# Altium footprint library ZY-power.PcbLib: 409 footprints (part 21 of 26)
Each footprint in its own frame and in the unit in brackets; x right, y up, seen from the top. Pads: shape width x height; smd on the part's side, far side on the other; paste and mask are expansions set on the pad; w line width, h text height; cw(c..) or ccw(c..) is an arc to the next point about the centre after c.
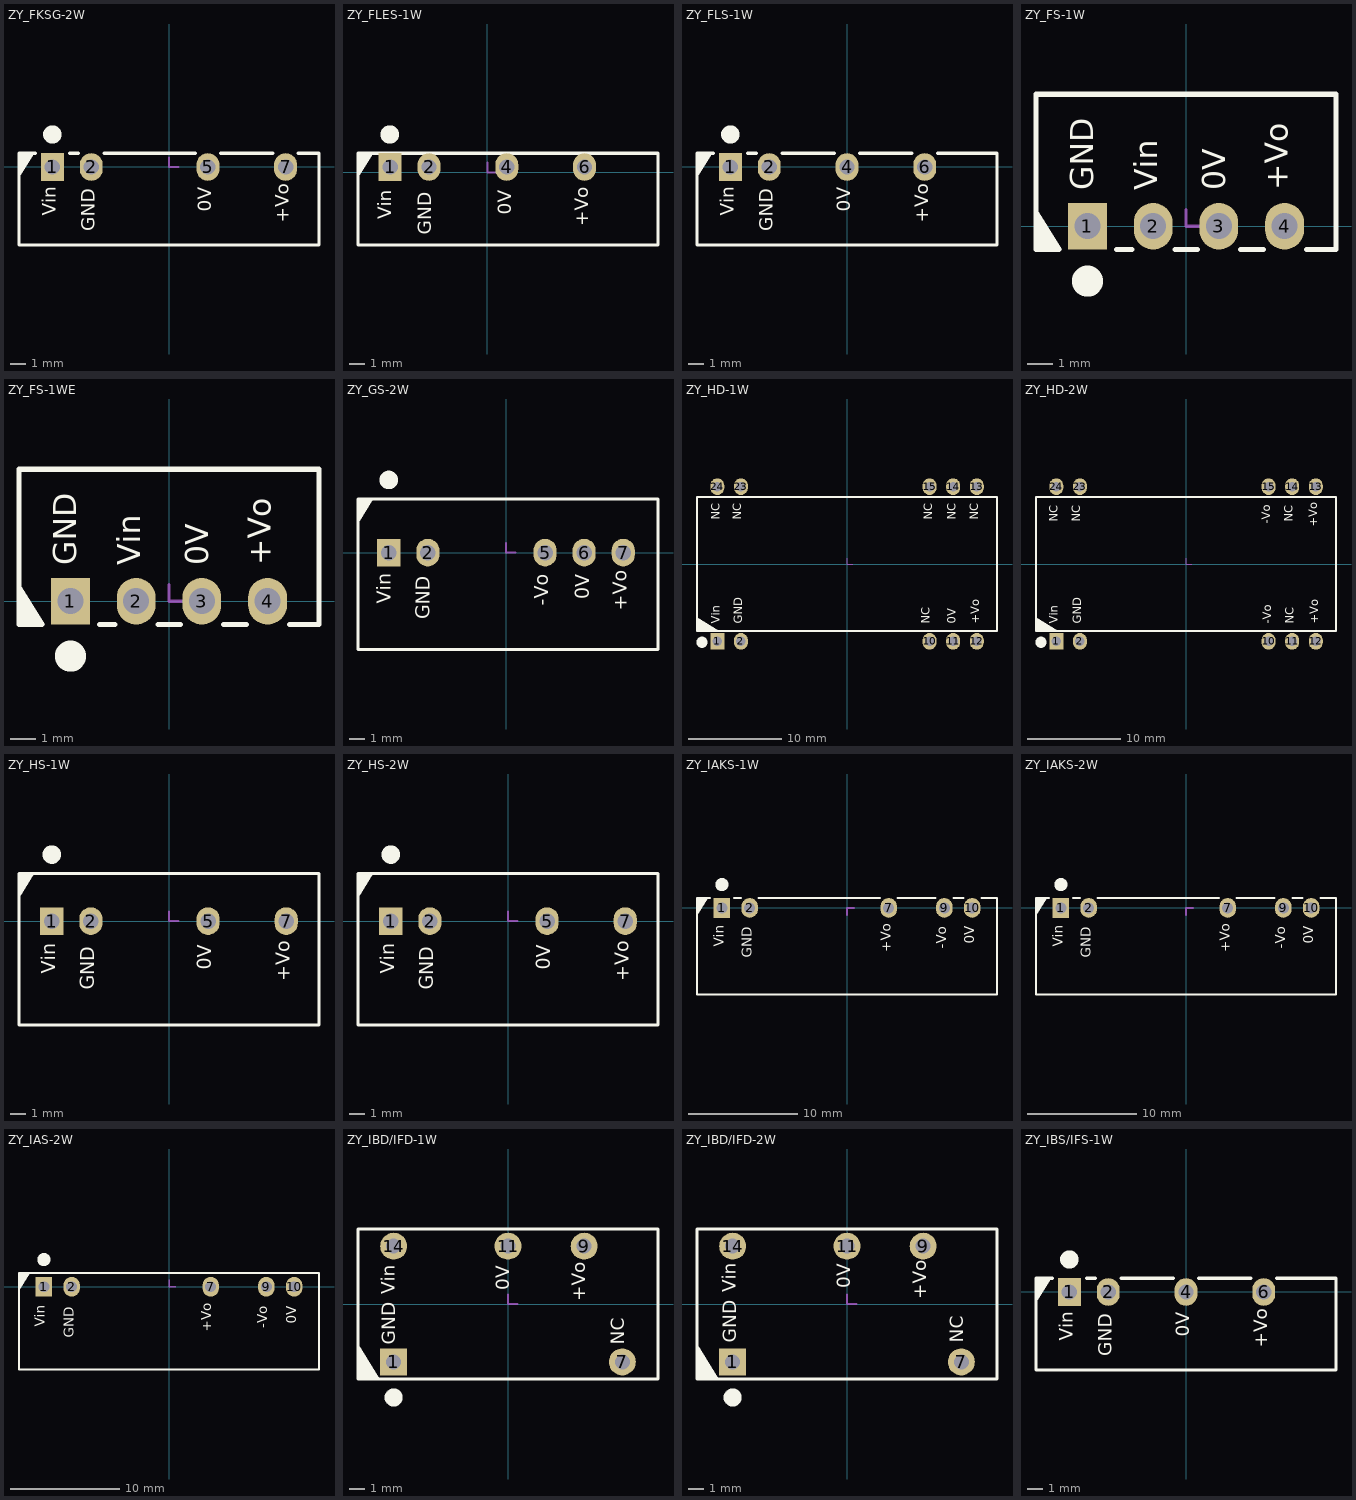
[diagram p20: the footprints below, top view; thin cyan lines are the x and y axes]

## ZY_FKSG-2W [mm]
height 10.1
pads (4):
  rect 1.5x1.8 hole 1: 1(-7.62,0)
  oval 1.5x1.8 hole 1: 2(-5.08,0) 5(2.54,0) 7(7.62,0)
Top Overlay:
  circle w1: c-7.62,2.125 r0.1
  region: -9.8,-0.686 -9.8,0.9 -8.806,0.9
  lines w0.2: -8.72,0.9 -9.8,0.9 -9.8,-5.1 9.8,-5.1 9.8,0.9 8.44,0.9 ; -6.5,0.9 -5.9,0.9 ; -4.26,0.9 1.72,0.9 ; 3.36,0.9 6.8,0.9
  text "+Vo" at 8.128,-3.649 h1.52
  text "0V" at 3.048,-2.909 h1.52
  text "GND" at -4.572,-4.191 h1.52
  text "Vin" at -7.112,-3.181 h1.52
Mechanical 15:
  lines w0.127: 0,0.635 0,0 0.635,0
3D body: height 10.1, standoff 0, extent -9.8,-5.1 9.8,0.9
3D body "zhenjao01.stp": height 8.36, standoff -4.08, extent 6.92,-1.48 8.32,0.12
3D body "zhenjao01.stp": height 8.36, standoff -4.08, extent 1.84,-1.48 3.24,0.12
3D body "zhenjao01.stp": height 8.36, standoff -4.08, extent -5.78,-1.48 -4.38,0.12
3D body "zhenjao01.stp": height 8.36, standoff -4.08, extent -8.32,-1.48 -6.92,0.12

## ZY_FLES-1W [mm]
height 10.1
pads (4):
  rect 1.5x1.8 hole 1: 1(-6.35,0.35)
  oval 1.5x1.8 hole 1: 2(-3.81,0.35) 4(1.27,0.35) 6(6.35,0.35)
Top Overlay:
  circle w1: c-6.374,2.475 r0.1
  region: -8.45,-0.336 -8.45,1.25 -7.456,1.25
  lines w0.2: -8.45,-4.75 11.15,-4.75 11.15,1.25 -8.45,1.25 -8.45,-4.75
  text "+Vo" at 6.883,-3.522 h1.52
  text "0V" at 1.854,-2.782 h1.52
  text "GND" at -3.378,-4.064 h1.52
  text "Vin" at -5.969,-3.054 h1.52
Mechanical 15:
  lines w0.127: 0,0.635 0,0 0.635,0

## ZY_FLS-1W [mm]
height 10.1
pads (4):
  rect 1.5x1.8 hole 1: 1(-7.62,0)
  oval 1.5x1.8 hole 1: 2(-5.08,0) 4(0,0) 6(5.08,0)
Top Overlay:
  circle w1: c-7.62,2.125 r0.1
  region: -9.8,-0.686 -9.8,0.9 -8.806,0.9
  lines w0.2: -8.72,0.9 -9.8,0.9 -9.8,-5.1 9.8,-5.1 9.8,0.9 5.9,0.9 ; -6.5,0.9 -5.9,0.9 ; -4.26,0.9 -0.82,0.9 ; 0.82,0.9 4.26,0.9
  text "+Vo" at 5.588,-3.649 h1.52
  text "0V" at 0.508,-2.909 h1.52
  text "GND" at -4.572,-4.191 h1.52
  text "Vin" at -7.112,-3.181 h1.52
Mechanical 15:
  lines w0.127: 0,0.635 0,0 0.635,0
3D body: height 10.1, standoff 0, extent -9.8,-5.1 9.8,0.9
3D body "zhenjao01.stp": height 8.36, standoff -4.08, extent 4.38,-1.48 5.78,0.12
3D body "zhenjao01.stp": height 8.36, standoff -4.08, extent -0.7,-1.48 0.7,0.12
3D body "zhenjao01.stp": height 8.36, standoff -4.08, extent -5.78,-1.48 -4.38,0.12
3D body "zhenjao01.stp": height 8.36, standoff -4.08, extent -8.32,-1.48 -6.92,0.12

## ZY_FS-1W [mm] "定压输入隔离非稳压单输出"
height 10.1
pads (4):
  rect 1.5x1.8 hole 1: 1(-3.81,0)
  oval 1.5x1.8 hole 1: 2(-1.27,0) 3(1.27,0) 4(3.81,0)
Top Overlay:
  circle w1: c-3.81,-2.125 r0.1
  region: -5.8,0.686 -5.8,-0.889 -4.813,-0.889
  lines w0.2: -4.91,-0.9 -5.8,-0.9 -5.8,5.1 5.8,5.1 5.8,-0.9 4.656,-0.9 ; -2.69,-0.9 -2.09,-0.9 ; -0.424,-0.9 0.45,-0.9 ; 2.116,-0.9 2.99,-0.9
  text "GND" at -3.302,1.396 h1.52
  text "Vin" at -0.813,1.397 h1.52
  text "0V" at 1.803,1.396 h1.52
  text "+Vo" at 4.216,1.396 h1.52
Mechanical 15:
  lines w0.127: 0,0.635 0,0 0.635,0
3D body "zhenjao01.stp": height 8.36, standoff -4.08, extent 3.11,-0.12 4.51,1.48
3D body "zhenjao01.stp": height 8.36, standoff -4.08, extent 0.57,-0.12 1.97,1.48
3D body "zhenjao01.stp": height 8.36, standoff -4.08, extent -1.97,-0.12 -0.57,1.48
3D body: height 10.1, standoff 0, extent -5.8,-0.9 5.8,5.1
3D body "zhenjao01.stp": height 8.36, standoff -4.08, extent -4.51,-0.12 -3.11,1.48

## ZY_FS-1WE [mm] "定压输入隔离非稳压单输出"
height 10.1
pads (4):
  rect 1.5x1.8 hole 1: 1(-3.81,0)
  oval 1.5x1.8 hole 1: 2(-1.27,0) 3(1.27,0) 4(3.81,0)
Top Overlay:
  circle w1: c-3.81,-2.125 r0.1
  region: -5.8,0.686 -5.8,-0.889 -4.813,-0.889
  lines w0.2: -4.91,-0.9 -5.8,-0.9 -5.8,5.1 5.8,5.1 5.8,-0.9 4.656,-0.9 ; -2.69,-0.9 -2.09,-0.9 ; -0.424,-0.9 0.45,-0.9 ; 2.116,-0.9 2.99,-0.9
  text "GND" at -3.302,1.396 h1.52
  text "Vin" at -0.813,1.397 h1.52
  text "0V" at 1.803,1.396 h1.52
  text "+Vo" at 4.216,1.396 h1.52
Mechanical 15:
  lines w0.127: 0,0.635 0,0 0.635,0
3D body "zhenjao01.stp": height 8.36, standoff -4.08, extent 3.11,-0.12 4.51,1.48
3D body "zhenjao01.stp": height 8.36, standoff -4.08, extent 0.57,-0.12 1.97,1.48
3D body "zhenjao01.stp": height 8.36, standoff -4.08, extent -1.97,-0.12 -0.57,1.48
3D body: height 10.1, standoff 0, extent -5.8,-0.9 5.8,5.1
3D body "zhenjao01.stp": height 8.36, standoff -4.08, extent -4.51,-0.12 -3.11,1.48

## ZY_GS-2W [mm]
pads (5):
  rect 1.5x1.8 hole 1 unplated: 1(-7.62,0)
  oval 1.5x1.8 hole 1 unplated: 2(-5.08,0) 5(2.54,0) 6(5.08,0) 7(7.62,0)
Top Overlay:
  circle w1: c-7.62,4.725 r0.1
  region: -9.62,1.914 -9.62,3.5 -8.626,3.5
  lines w0.2: -9.62,-6.3 -9.62,3.5 9.88,3.5 9.88,-6.3 -9.62,-6.3
  text "+Vo" at 8.128,-3.776 h1.52
  text "-Vo" at 3.048,-3.464 h1.52
  text "0V" at 5.715,-3.036 h1.52
  text "GND" at -4.667,-4.318 h1.52
  text "Vin" at -7.207,-3.308 h1.52
Mechanical 15:
  lines w0.127: 0,0.635 0,0 0.635,0

## ZY_HD-1W [mm]
pads (10):
  rect 1.5x1.8 hole 1: 1(-13.97,-8.325)
  oval 1.5x1.8 hole 1: 2(-11.43,-8.325) 10(8.89,-8.325) 11(11.43,-8.325) 12(13.97,-8.325) 13(13.97,8.325) 14(11.43,8.325) 15(8.89,8.325) 23(-11.43,8.325) 24(-13.97,8.325)
Top Overlay:
  circle w1: c-15.621,-8.425 r0.1
  region: -13.824,-7.2 -16.154,-7.2 -16.154,-5.74
  lines w0.2: -16.154,-7.2 16.146,-7.2 16.146,7.2 -16.154,7.2 -16.154,-7.2
  text "NC" at -13.36,4.769 h1.52
  text "NC" at -11.074,4.769 h1.52
  text "NC" at 14.453,4.769 h1.52
  text "NC" at 12.04,4.769 h1.52
  text "NC" at 9.5,4.769 h1.52
  text "+Vo" at 14.58,-6.421 h1.52
  text "0V" at 12.04,-6.421 h1.52
  text "NC" at 9.246,-6.421 h1.52
  text "GND" at -10.947,-6.421 h1.52
  text "Vin" at -13.36,-6.42 h1.52
Mechanical 15:
  lines w0.127: 0,0.635 0,0 0.635,0

## ZY_HD-2W [mm]
pads (10):
  rect 1.5x1.8 hole 1: 1(-13.97,-8.325)
  oval 1.5x1.8 hole 1: 2(-11.43,-8.325) 10(8.89,-8.325) 11(11.43,-8.325) 12(13.97,-8.325) 13(13.97,8.325) 14(11.43,8.325) 15(8.89,8.325) 23(-11.43,8.325) 24(-13.97,8.325)
Top Overlay:
  circle w1: c-15.621,-8.425 r0.1
  region: -13.824,-7.2 -16.154,-7.2 -16.154,-5.74
  lines w0.2: -16.154,-7.2 16.146,-7.2 16.146,7.2 -16.154,7.2 -16.154,-7.2
  text "NC" at -13.487,4.536 h1.52
  text "NC" at -11.074,4.536 h1.52
  text "+Vo" at 14.58,-6.421 h1.52
  text "GND" at -10.947,-6.421 h1.52
  text "Vin" at -13.487,-6.42 h1.52
  text "-Vo" at 9.5,-6.421 h1.52
  text "NC" at 11.913,-6.421 h1.52
  text "NC" at 11.786,4.536 h1.52
  text "-Vo" at 9.373,4.319 h1.52
  text "+Vo" at 14.453,4.007 h1.52
Mechanical 15:
  lines w0.127: 0,0.635 0,0 0.635,0

## ZY_HS-1W [mm]
pads (4):
  rect 1.5x1.8 hole 1: 1(-7.62,0)
  oval 1.5x1.8 hole 1: 2(-5.08,0) 5(2.54,0) 7(7.62,0)
Top Overlay:
  circle w1: c-7.62,4.325 r0.1
  region: -9.75,1.504 -9.75,3.1 -8.75,3.1
  lines w0.2: -9.75,-6.75 -9.75,3.1 9.75,3.1 9.75,-6.75 -9.75,-6.75
  text "Vin" at -7.112,-3.435 h1.52
  text "GND" at -4.572,-4.445 h1.52
  text "0V" at 3.048,-3.163 h1.52
  text "+Vo" at 8.128,-3.903 h1.52
Mechanical 15:
  lines w0.127: 0,0.635 0,0 0.635,0
3D body "zhenjao01.stp": height 8.36, standoff -4.08, extent -8.32,-1.48 -6.92,0.12
3D body "zhenjao01.stp": height 8.36, standoff -4.08, extent -5.78,-1.48 -4.38,0.12
3D body "zhenjao01.stp": height 8.36, standoff -4.08, extent 1.84,-1.48 3.24,0.12
3D body "zhenjao01.stp": height 8.36, standoff -4.08, extent 6.92,-1.48 8.32,0.12
3D body: height 12.5, standoff 0, extent -9.75,-6.75 9.75,3.1

## ZY_HS-2W [mm]
height 12.5
pads (4):
  rect 1.5x1.8 hole 1: 1(-7.62,0)
  oval 1.5x1.8 hole 1: 2(-5.08,0) 5(2.54,0) 7(7.62,0)
Top Overlay:
  circle w1: c-7.62,4.325 r0.1
  region: -9.75,1.504 -9.75,3.1 -8.75,3.1
  lines w0.2: -9.75,-6.75 -9.75,3.1 9.75,3.1 9.75,-6.75 -9.75,-6.75
  text "Vin" at -7.112,-3.435 h1.52
  text "GND" at -4.572,-4.445 h1.52
  text "0V" at 3.048,-3.163 h1.52
  text "+Vo" at 8.128,-3.903 h1.52
Mechanical 15:
  lines w0.127: 0,0.635 0,0 0.635,0
3D body "zhenjao01.stp": height 8.36, standoff -4.08, extent -8.32,-1.48 -6.92,0.12
3D body "zhenjao01.stp": height 8.36, standoff -4.08, extent -5.78,-1.48 -4.38,0.12
3D body "zhenjao01.stp": height 8.36, standoff -4.08, extent 1.84,-1.48 3.24,0.12
3D body "zhenjao01.stp": height 8.36, standoff -4.08, extent 6.92,-1.48 8.32,0.12
3D body: height 12.5, standoff 0, extent -9.75,-6.75 9.75,3.1

## ZY_IAKS-1W [mm] "定压输入隔离稳压双输出"
height 11.4
pads (5):
  rect 1.5x1.8 hole 1: 1(-11.43,0)
  oval 1.5x1.8 hole 1: 2(-8.89,0) 7(3.81,0) 9(8.89,0) 10(11.43,0)
Top Overlay:
  circle w1: c-11.43,2.125 r0.1
  region: -13.7,-0.686 -13.7,0.9 -12.706,0.9
  lines w0.2: -12.53,0.9 -13.7,0.9 -13.7,-7.9 13.7,-7.9 13.7,0.9 12.276,0.9 ; -10.31,0.9 -9.71,0.9 ; -8.07,0.9 2.99,0.9 ; 4.63,0.9 8.07,0.9 ; 9.736,0.9 10.61,0.9
  text "Vin" at -10.935,-3.562 h1.52
  text "GND" at -8.395,-4.572 h1.52
  text "+Vo" at 4.305,-4.03 h1.52
  text "-Vo" at 9.385,-3.718 h1.52
  text "0V" at 11.925,-3.29 h1.52
Mechanical 15:
  lines w0.203: 0,-0.635 0,0 0.635,0
3D body "zhenjao01.stp": height 8.36, standoff -4.08, extent -12.13,-1.48 -10.73,0.12
3D body "zhenjao01.stp": height 8.36, standoff -4.08, extent -9.59,-1.48 -8.19,0.12
3D body "zhenjao01.stp": height 8.36, standoff -4.08, extent 3.11,-1.48 4.51,0.12
3D body "zhenjao01.stp": height 8.36, standoff -4.08, extent 8.19,-1.48 9.59,0.12
3D body "zhenjao01.stp": height 8.36, standoff -4.08, extent 10.73,-1.48 12.13,0.12
3D body: height 11.4, standoff 0, extent -13.7,-7.9 13.7,0.9

## ZY_IAKS-2W [mm]
height 11.4
pads (5):
  rect 1.5x1.8 hole 1: 1(-11.43,0)
  oval 1.5x1.8 hole 1: 2(-8.89,0) 7(3.81,0) 9(8.89,0) 10(11.43,0)
Top Overlay:
  circle w1: c-11.43,2.125 r0.1
  region: -13.7,-0.686 -13.7,0.9 -12.706,0.9
  lines w0.2: -12.53,0.9 -13.7,0.9 -13.7,-7.9 13.7,-7.9 13.7,0.9 12.276,0.9 ; -10.31,0.9 -9.71,0.9 ; -8.07,0.9 2.99,0.9 ; 4.63,0.9 8.07,0.9 ; 9.736,0.9 10.61,0.9
  text "0V" at 11.925,-3.29 h1.52
  text "-Vo" at 9.385,-3.718 h1.52
  text "+Vo" at 4.305,-4.03 h1.52
  text "GND" at -8.395,-4.572 h1.52
  text "Vin" at -10.935,-3.562 h1.52
Mechanical 15:
  lines w0.203: 0,-0.635 0,0 0.635,0
3D body: height 11.4, standoff 0, extent -13.7,-7.9 13.7,0.9
3D body "zhenjao01.stp": height 8.36, standoff -4.08, extent 10.73,-1.48 12.13,0.12
3D body "zhenjao01.stp": height 8.36, standoff -4.08, extent 8.19,-1.48 9.59,0.12
3D body "zhenjao01.stp": height 8.36, standoff -4.08, extent 3.11,-1.48 4.51,0.12
3D body "zhenjao01.stp": height 8.36, standoff -4.08, extent -9.59,-1.48 -8.19,0.12
3D body "zhenjao01.stp": height 8.36, standoff -4.08, extent -12.13,-1.48 -10.73,0.12

## ZY_IAS-2W [mm]
height 10.1
pads (5):
  rect 1.5x1.8 hole 1: 1(-11.43,0)
  oval 1.5x1.8 hole 1: 2(-8.89,0) 7(3.81,0) 9(8.89,0) 10(11.43,0)
Top Overlay:
  circle w1: c-11.43,2.475 r0.1
  region: -13.7,-0.336 -13.7,1.25 -12.706,1.25
  lines w0.2: -13.7,-7.55 -13.7,1.25 13.7,1.25 13.7,-7.55 -13.7,-7.55
  text "0V" at 11.938,-3.375 h1.52
  text "-Vo" at 9.271,-3.802 h1.52
  text "+Vo" at 4.191,-4.115 h1.52
  text "GND" at -8.382,-4.657 h1.52
  text "Vin" at -11.049,-3.646 h1.52
Mechanical 15:
  lines w0.127: 0,0.635 0,0 0.635,0

## ZY_IBD/IFD-1W [mm]
height 8.1
pads (5):
  rect 1.8x1.8 hole 1: 1(-7.62,-3.86)
  round 1.8 hole 1: 7(7.62,-3.86) 9(5.08,3.86) 11(0,3.86) 14(-7.62,3.86)
Top Overlay:
  circle w1: c-7.62,-6.225 r0.1
  region: -10,-2.67 -10,-5 -8.54,-5
  lines w0.2: -10,-5 10,-5 10,5 -10,5 -10,-5
  text "GND" at -7.206,-2.714 h1.52
  text "NC" at 8.034,-2.714 h1.52
  text "+Vo" at 5.461,0.18 h1.52
  text "0V" at 0.381,0.92 h1.52
  text "Vin" at -7.239,0.648 h1.52
Mechanical 15:
  lines w0.127: 0,0.635 0,0 0.635,0

## ZY_IBD/IFD-2W [mm]
pads (5):
  rect 1.8x1.8 hole 1: 1(-7.62,-3.86)
  round 1.8 hole 1: 7(7.62,-3.86) 9(5.08,3.86) 11(0,3.86) 14(-7.62,3.86)
Top Overlay:
  circle w1: c-7.62,-6.225 r0.1
  region: -10,-2.67 -10,-5 -8.54,-5
  lines w0.2: -10,-5 -10,5 10,5 10,-5 -10,-5
  text "Vin" at -7.112,0.775 h1.52
  text "0V" at 0.508,1.047 h1.52
  text "+Vo" at 5.588,0.307 h1.52
  text "NC" at 8.034,-2.587 h1.52
  text "GND" at -7.079,-2.587 h1.52
Mechanical 15:
  lines w0.127: 0,0.635 0,0 0.635,0

## ZY_IBS/IFS-1W [mm] "定压输入隔离稳压单输出"
height 10.1
pads (4):
  rect 1.5x1.8 hole 1: 1(-7.62,0)
  oval 1.5x1.8 hole 1: 2(-5.08,0) 4(0,0) 6(5.08,0)
Top Overlay:
  circle w1: c-7.62,2.125 r0.1
  region: -9.8,-0.686 -9.8,0.9 -8.806,0.9
  lines w0.2: -8.72,0.9 -9.8,0.9 -9.8,-5.1 9.8,-5.1 9.8,0.9 5.9,0.9 ; -6.5,0.9 -5.9,0.9 ; -4.26,0.9 -0.82,0.9 ; 0.82,0.9 4.26,0.9
  text "+Vo" at 5.588,-3.649 h1.52
  text "0V" at 0.508,-2.909 h1.52
  text "GND" at -4.572,-4.191 h1.52
  text "Vin" at -7.112,-3.181 h1.52
Mechanical 15:
  lines w0.127: 0,0.635 0,0 0.635,0
3D body: height 10.1, standoff 0, extent -9.8,-5.1 9.8,0.9
3D body "zhenjao01.stp": height 8.36, standoff -4.08, extent 4.38,-1.48 5.78,0.12
3D body "zhenjao01.stp": height 8.36, standoff -4.08, extent -0.7,-1.48 0.7,0.12
3D body "zhenjao01.stp": height 8.36, standoff -4.08, extent -5.78,-1.48 -4.38,0.12
3D body "zhenjao01.stp": height 8.36, standoff -4.08, extent -8.32,-1.48 -6.92,0.12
